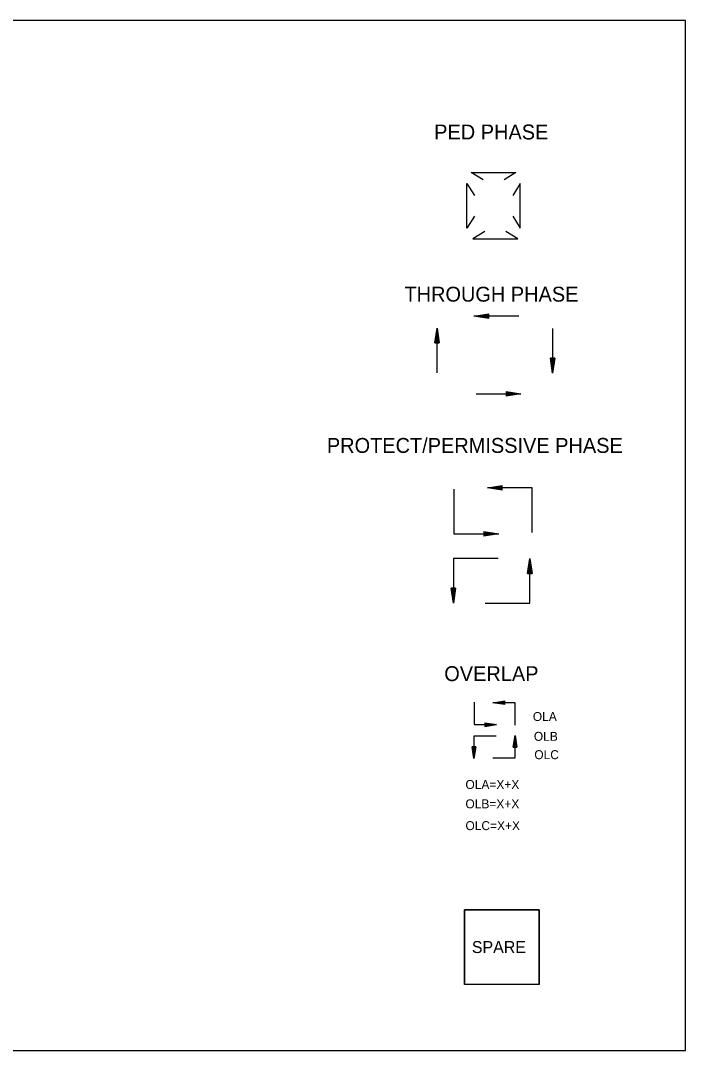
# Model space of a CAD drawing. Extents: x -218554 to 420114, y -565956 to -483460.
# Drawn here: x 418625.5 to 418728.9, y -565630.3 to -565470.3 of the extents above; entities that cross this region are included whole.
import ezdxf

# ---------------------------------------------------------------- set-up
doc = ezdxf.new("R2010")
doc.units = 0
doc.layers.add('Level 57', color=7, linetype='Continuous')
doc.layers.add('Template', color=7, linetype='Continuous')

msp = doc.modelspace()

# ---------------------------------------------------------------- linework, layer by layer
at = {"layer": 'Level 57'}
for p, q in [((418695.99, -565516.22), (418698.31, -565515.87)), ((418698.31, -565515.93), (418696.38, -565516.22)), ((418696.78, -565516.22), (418698.31, -565515.99)), ((418698.31, -565516.05), (418697.16, -565516.22)), ((418697.56, -565516.22), (418698.31, -565516.11)), ((418698.31, -565516.57), (418698.31, -565515.87)), ((418702.95, -565516.22), (418695.99, -565516.22)), ((418698.31, -565516.57), (418695.99, -565516.22)), ((418696.38, -565516.22), (418698.31, -565516.51)), ((418698.31, -565516.45), (418696.78, -565516.22)), ((418697.16, -565516.22), (418698.31, -565516.39)), ((418698.31, -565516.33), (418697.56, -565516.22)), ((418698.31, -565516.17), (418697.94, -565516.22)), ((418697.94, -565516.22), (418698.31, -565516.27)), ((418689.9, -565520.39), (418690.25, -565518.07)), ((418690.25, -565518.45), (418689.96, -565520.39)), ((418690.02, -565520.39), (418690.25, -565518.85)), ((418690.25, -565519.24), (418690.08, -565520.39)), ((418690.25, -565525.02), (418690.25, -565518.07)), ((418690.25, -565518.07), (418690.6, -565520.39)), ((418690.54, -565520.39), (418690.25, -565518.45)), ((418690.25, -565518.85), (418690.48, -565520.39)), ((418690.42, -565520.39), (418690.25, -565519.24)), ((418708.22, -565518.14), (418708.22, -565525.09)), ((418689.9, -565520.39), (418690.6, -565520.39)), ((418690.14, -565520.39), (418690.25, -565519.63)), ((418690.25, -565520.02), (418690.19, -565520.39)), ((418690.25, -565519.63), (418690.36, -565520.39)), ((418690.3, -565520.39), (418690.25, -565520.02)), ((418708.22, -565525.09), (418707.87, -565522.77)), ((418708.57, -565522.77), (418707.87, -565522.77)), ((418707.93, -565522.77), (418708.22, -565524.71)), ((418708.22, -565524.31), (418707.99, -565522.77)), ((418708.05, -565522.77), (418708.22, -565523.92)), ((418708.22, -565523.53), (418708.11, -565522.77)), ((418708.17, -565522.77), (418708.22, -565523.14)), ((418708.22, -565523.14), (418708.28, -565522.77)), ((418708.33, -565522.77), (418708.22, -565523.53)), ((418708.22, -565523.92), (418708.39, -565522.77)), ((418708.45, -565522.77), (418708.22, -565524.31)), ((418708.22, -565524.71), (418708.51, -565522.77)), ((418708.57, -565522.77), (418708.22, -565525.09)), ((418696.33, -565528.3), (418703.29, -565528.3)), ((418700.97, -565527.95), (418703.29, -565528.3)), ((418700.97, -565527.95), (418700.97, -565528.65)), ((418702.9, -565528.3), (418700.97, -565528.01)), ((418700.97, -565528.07), (418702.5, -565528.3)), ((418702.12, -565528.3), (418700.97, -565528.13)), ((418700.97, -565528.19), (418701.72, -565528.3)), ((418701.34, -565528.3), (418700.97, -565528.24)), ((418703.29, -565528.3), (418700.97, -565528.65)), ((418700.97, -565528.59), (418702.9, -565528.3)), ((418702.5, -565528.3), (418700.97, -565528.53)), ((418700.97, -565528.47), (418702.12, -565528.3)), ((418701.72, -565528.3), (418700.97, -565528.41)), ((418700.97, -565528.35), (418701.34, -565528.3)), ((418692.88, -565543.11), (418692.88, -565550.07)), ((418698.07, -565542.91), (418700.39, -565542.57)), ((418705.03, -565542.91), (418698.07, -565542.91)), ((418700.39, -565543.26), (418698.07, -565542.91)), ((418700.39, -565542.62), (418698.46, -565542.91)), ((418698.46, -565542.91), (418700.39, -565543.2)), ((418698.86, -565542.91), (418700.39, -565542.68)), ((418700.39, -565543.15), (418698.86, -565542.91)), ((418700.39, -565542.74), (418699.24, -565542.91)), ((418699.24, -565542.91), (418700.39, -565543.09)), ((418699.63, -565542.91), (418700.39, -565542.8)), ((418700.39, -565543.03), (418699.63, -565542.91)), ((418700.39, -565542.86), (418700.02, -565542.91)), ((418700.02, -565542.91), (418700.39, -565542.97)), ((418700.39, -565543.26), (418700.39, -565542.57)), ((418705.03, -565549.87), (418705.03, -565542.91)), ((418697.52, -565549.72), (418699.84, -565550.07)), ((418697.52, -565549.72), (418697.52, -565550.41)), ((418692.88, -565550.07), (418699.84, -565550.07)), ((418699.45, -565550.07), (418697.52, -565549.78)), ((418697.52, -565549.84), (418699.05, -565550.07)), ((418698.67, -565550.07), (418697.52, -565549.89)), ((418697.52, -565549.95), (418698.28, -565550.07)), ((418697.89, -565550.07), (418697.52, -565550.01)), ((418699.84, -565550.07), (418697.52, -565550.41)), ((418697.52, -565550.36), (418699.45, -565550.07)), ((418699.05, -565550.07), (418697.52, -565550.3)), ((418697.52, -565550.24), (418698.67, -565550.07)), ((418698.28, -565550.07), (418697.52, -565550.18)), ((418697.52, -565550.12), (418697.89, -565550.07)), ((418699.75, -565553.88), (418692.79, -565553.88)), ((418692.79, -565553.88), (418692.79, -565560.84)), ((418704.33, -565556.2), (418704.67, -565553.88)), ((418704.67, -565554.26), (418704.38, -565556.2)), ((418704.67, -565560.83), (418704.67, -565553.88)), ((418704.67, -565553.88), (418705.02, -565556.2)), ((418704.96, -565556.2), (418704.67, -565554.26)), ((418704.44, -565556.2), (418704.67, -565554.66)), ((418704.67, -565555.05), (418704.5, -565556.2)), ((418704.56, -565556.2), (418704.67, -565555.44)), ((418704.67, -565555.83), (418704.62, -565556.2)), ((418704.67, -565554.66), (418704.9, -565556.2)), ((418704.85, -565556.2), (418704.67, -565555.05)), ((418704.67, -565555.44), (418704.79, -565556.2)), ((418704.73, -565556.2), (418704.67, -565555.83)), ((418704.33, -565556.2), (418705.02, -565556.2)), ((418692.79, -565560.84), (418692.44, -565558.52)), ((418693.14, -565558.52), (418692.44, -565558.52)), ((418692.5, -565558.52), (418692.79, -565560.45)), ((418692.79, -565560.05), (418692.56, -565558.52)), ((418692.62, -565558.52), (418692.79, -565559.67)), ((418692.79, -565559.27), (418692.68, -565558.52)), ((418692.74, -565558.52), (418692.79, -565558.89)), ((418692.79, -565558.89), (418692.85, -565558.52)), ((418692.9, -565558.52), (418692.79, -565559.27)), ((418692.79, -565559.67), (418692.96, -565558.52)), ((418693.02, -565558.52), (418692.79, -565560.05)), ((418692.79, -565560.45), (418693.08, -565558.52)), ((418693.14, -565558.52), (418692.79, -565560.84)), ((418697.72, -565560.83), (418704.67, -565560.83)), ((418696.02, -565576.23), (418696.02, -565579.71)), ((418698.91, -565576.31), (418700.77, -565576.03)), ((418702.39, -565576.31), (418698.91, -565576.31)), ((418700.77, -565576.59), (418698.91, -565576.31)), ((418700.77, -565576.08), (418699.22, -565576.31)), ((418699.22, -565576.31), (418700.77, -565576.54)), ((418699.54, -565576.31), (418700.77, -565576.12)), ((418700.77, -565576.49), (418699.54, -565576.31)), ((418700.77, -565576.17), (418699.85, -565576.31)), ((418699.85, -565576.31), (418700.77, -565576.45)), ((418700.16, -565576.31), (418700.77, -565576.22)), ((418700.77, -565576.4), (418700.16, -565576.31)), ((418700.77, -565576.26), (418700.47, -565576.31)), ((418700.47, -565576.31), (418700.77, -565576.35)), ((418700.77, -565576.59), (418700.77, -565576.03)), ((418702.39, -565579.79), (418702.39, -565576.31)), ((418696.02, -565579.71), (418699.5, -565579.71)), ((418697.65, -565579.43), (418699.5, -565579.71)), ((418697.65, -565579.43), (418697.65, -565579.99)), ((418697.65, -565579.43), (418699.5, -565579.71)), ((418697.65, -565579.43), (418697.65, -565579.99)), ((418697.65, -565579.48), (418699.19, -565579.71)), ((418699.19, -565579.71), (418697.65, -565579.48)), ((418697.65, -565579.53), (418698.87, -565579.71)), ((418697.65, -565579.53), (418698.87, -565579.71)), ((418697.65, -565579.57), (418698.56, -565579.71)), ((418698.56, -565579.71), (418697.65, -565579.57)), ((418697.65, -565579.62), (418698.25, -565579.71)), ((418697.65, -565579.62), (418698.25, -565579.71)), ((418697.65, -565579.67), (418697.94, -565579.71)), ((418697.94, -565579.71), (418697.65, -565579.67)), ((418697.65, -565579.99), (418699.5, -565579.71)), ((418697.65, -565579.8), (418698.25, -565579.71)), ((418697.65, -565579.89), (418698.87, -565579.71)), ((418697.65, -565579.94), (418699.19, -565579.71)), ((418697.65, -565579.85), (418698.56, -565579.71)), ((418697.65, -565579.75), (418697.94, -565579.71)), ((418699.5, -565579.71), (418697.65, -565579.99)), ((418697.65, -565579.94), (418699.19, -565579.71)), ((418698.87, -565579.71), (418697.65, -565579.89)), ((418697.65, -565579.85), (418698.56, -565579.71)), ((418698.25, -565579.71), (418697.65, -565579.8)), ((418697.65, -565579.75), (418697.94, -565579.71)), ((418699.46, -565581.52), (418695.99, -565581.52)), ((418695.99, -565581.52), (418695.99, -565585)), ((418702.1, -565583.24), (418702.38, -565581.39)), ((418702.38, -565581.7), (418702.14, -565583.24)), ((418702.38, -565584.87), (418702.38, -565581.39)), ((418702.38, -565581.39), (418702.65, -565583.24)), ((418702.61, -565583.24), (418702.38, -565581.7)), ((418695.99, -565585), (418695.71, -565583.14)), ((418696.26, -565583.14), (418695.71, -565583.14)), ((418695.75, -565583.14), (418695.99, -565584.69)), ((418695.99, -565584.37), (418695.8, -565583.14)), ((418695.85, -565583.14), (418695.99, -565584.06)), ((418695.99, -565583.75), (418695.89, -565583.14)), ((418695.94, -565583.14), (418695.99, -565583.44)), ((418695.99, -565583.44), (418696.03, -565583.14)), ((418696.08, -565583.14), (418695.99, -565583.75)), ((418695.99, -565584.06), (418696.12, -565583.14)), ((418696.17, -565583.14), (418695.99, -565584.37)), ((418695.99, -565584.69), (418696.22, -565583.14)), ((418696.26, -565583.14), (418695.99, -565585)), ((418702.1, -565583.24), (418702.65, -565583.24)), ((418702.19, -565583.24), (418702.38, -565582.02)), ((418702.38, -565582.33), (418702.24, -565583.24)), ((418702.29, -565583.24), (418702.38, -565582.64)), ((418702.38, -565582.95), (418702.33, -565583.24)), ((418702.38, -565582.02), (418702.56, -565583.24)), ((418702.51, -565583.24), (418702.38, -565582.33)), ((418702.38, -565582.64), (418702.47, -565583.24)), ((418702.42, -565583.24), (418702.38, -565582.95)), ((418698.9, -565584.87), (418702.38, -565584.87)), ((418694.5, -565608.48), (418694.5, -565620.08)), ((418706.1, -565608.48), (418694.5, -565608.48)), ((418706.1, -565620.08), (418706.1, -565608.48))]:
    msp.add_line(p, q, dxfattribs=at)
for points in [[(418697.42, -565495.05), (418695.56, -565493.89), (418702.52, -565493.89), (418700.67, -565495.05)], [(418696.06, -565500.7), (418694.9, -565502.55), (418694.9, -565495.59), (418696.06, -565497.45)], [(418702.03, -565500.7), (418703.19, -565502.55), (418703.19, -565495.59), (418702.03, -565497.45)], [(418697.68, -565503.06), (418695.83, -565504.22), (418702.78, -565504.22), (418700.93, -565503.06)]]:
    msp.add_lwpolyline(points, dxfattribs=at)
msp.add_lwpolyline([(418694.5, -565608.48), (418706.1, -565608.48), (418706.1, -565620.08), (418694.5, -565620.08)], close=True, dxfattribs=at)
at = {"layer": 'Template'}
msp.add_lwpolyline([(418728.86, -565470.29), (418596.87, -565470.29), (418596.87, -565630.35), (418728.86, -565630.35)], close=True, dxfattribs=at)

# ---------------------------------------------------------------- texts
at = {"layer": 'Level 57'}
for s, height, p in [('PED PHASE', 2.319, (418689.8, -565488.76)), ('THROUGH PHASE', 2.3189, (418685.18, -565513.97)), ('PROTECT/PERMISSIVE PHASE', 2.3189, (418673.12, -565537.48)), ('OVERLAP', 2.319, (418691.37, -565572.95)), ('OLA', 1.391, (418705.14, -565579.15)), ('OLB', 1.391, (418705.3, -565582.23)), ('OLC', 1.391, (418705.37, -565585.08)), ('OLA=X+X', 1.391, (418694.66, -565589.71)), ('OLB=X+X', 1.391, (418694.66, -565592.72)), ('OLC=X+X', 1.391, (418694.66, -565596.11)), ('SPARE', 1.855, (418695.66, -565615.21))]:
    msp.add_text(s, height=height, rotation=360, dxfattribs=at).set_placement(p)

doc.saveas('drawing.dxf')
